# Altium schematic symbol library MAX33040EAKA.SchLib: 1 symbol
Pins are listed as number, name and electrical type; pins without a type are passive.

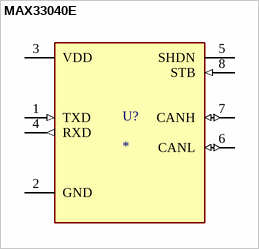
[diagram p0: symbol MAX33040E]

## MAX33040E
designator U?
+3.3V, 5Mbps CAN Transceiver with; MP: ATA6561-GBQW
footprint MAX33040EAKA
pins: 1 TXD (in), 2 GND (power), 3 VDD (power), 4 RXD (out), 5 SHDN (power), 6 CANL (io), 7 CANH (io), 8 STB (in)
